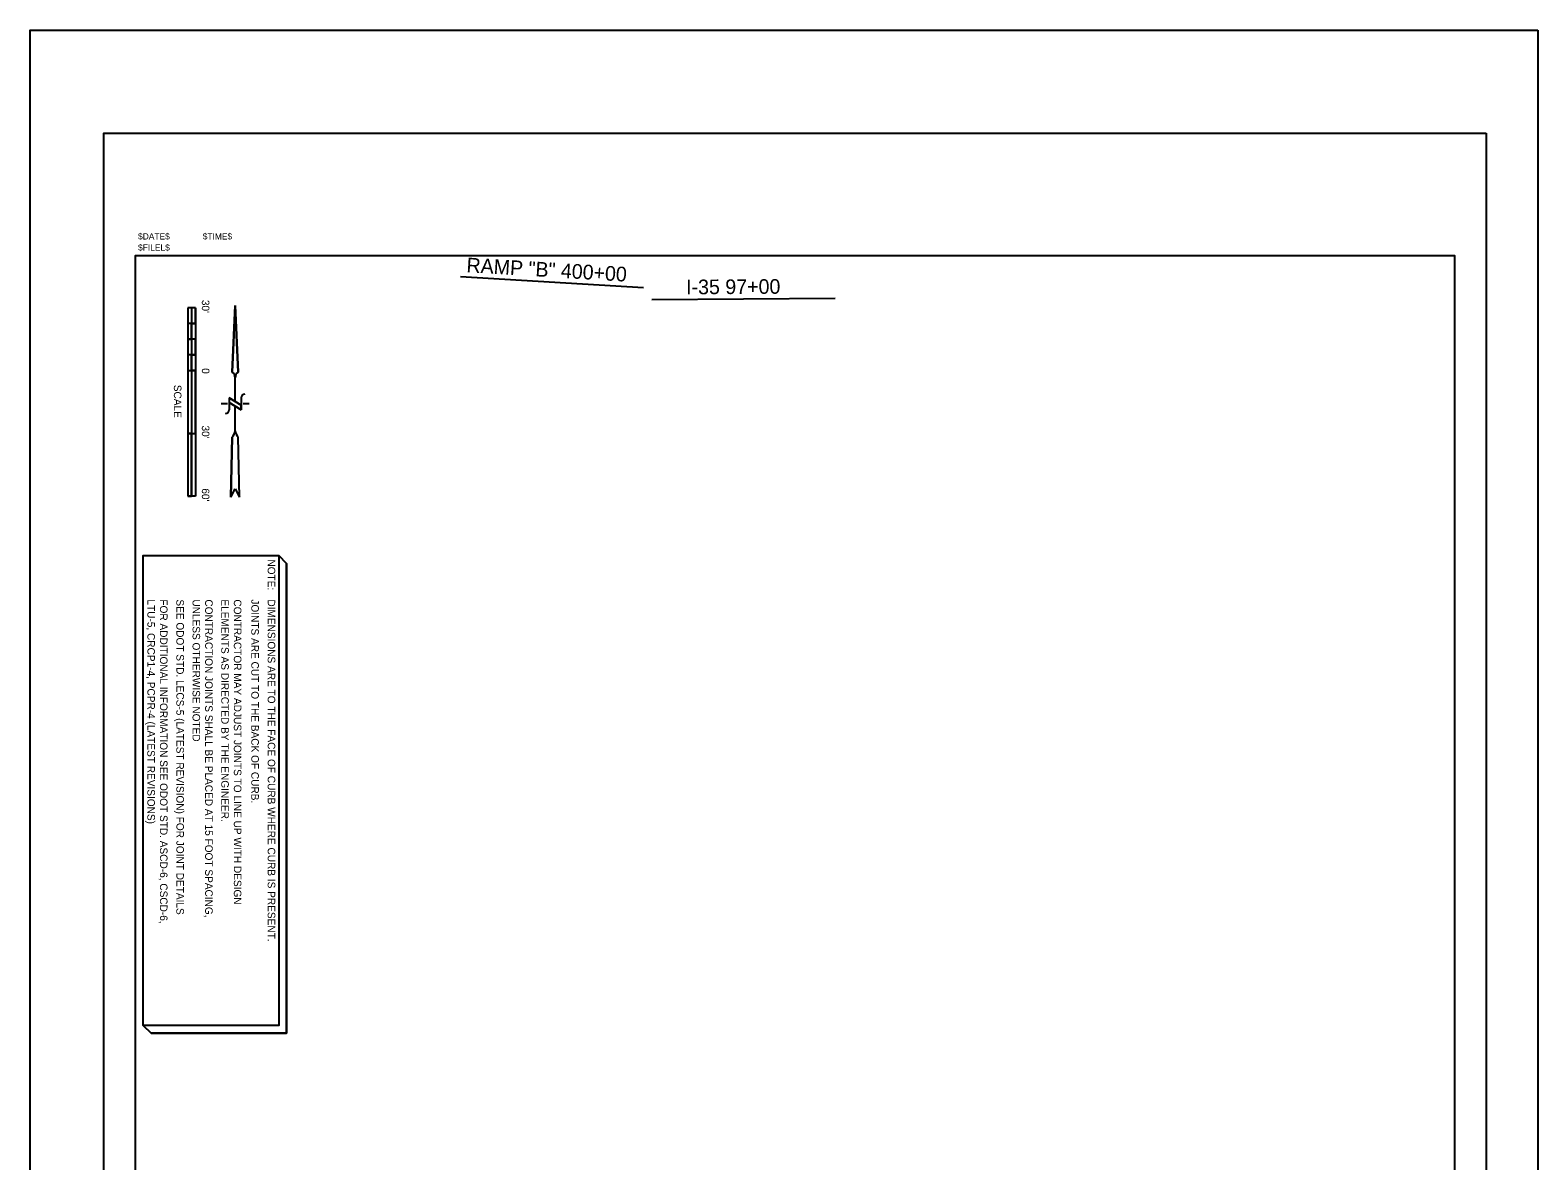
# Model space of a CAD drawing. Extents: x 2150474 to 2151194, y 143768 to 144848.
# Drawn here: x 2150474 to 2151194, y 144308 to 144848 of the extents above; entities that cross this region are included whole.
import ezdxf

# ---------------------------------------------------------------- set-up
doc = ezdxf.new("R2010")
doc.units = 0
for name, color, linetype in [('PR_Shading_1', 7, 'Continuous'), ('PR_Txt', 7, 'Continuous'), ('SHT_Match_Lines', 7, 'Continuous'), ('SHT_North_Arrow', 7, 'Continuous'), ('SHT_Plot_Shape_Full', 7, 'Continuous'), ('SHT_Plot_Shape_Half', 7, 'Continuous'), ('SHT_Plot_Stamp', 7, 'Continuous'), ('SHT_Scale', 7, 'Continuous'), ('SHT_Sheet_Border', 7, 'Continuous')]:
    doc.layers.add(name, color=color, linetype=linetype)

msp = doc.modelspace()

# ---------------------------------------------------------------- linework, layer by layer
at = {"layer": 'PR_Shading_1'}
msp.add_line((2150596.09, 144593.01), (2150592.34, 144596.76), dxfattribs=at)
for points in [[(2150592.34, 144596.76), (2150592.34, 144372.35), (2150527.66, 144372.35)], [(2150527.66, 144372.35), (2150531.41, 144368.6), (2150596.09, 144368.6), (2150596.09, 144593.01)]]:
    msp.add_lwpolyline(points, dxfattribs=at)
at = {"layer": 'PR_Txt'}
msp.add_lwpolyline([(2150592.34, 144596.76), (2150592.34, 144372.35), (2150527.66, 144372.35), (2150527.66, 144596.76)], close=True, dxfattribs=at)
msp.add_lwpolyline([(2150592.34, 144596.76), (2150596.09, 144593.01), (2150596.09, 144368.6), (2150531.41, 144368.6), (2150527.66, 144372.35)], dxfattribs=at)
at = {"layer": 'SHT_Match_Lines'}
for p, q in [((2150766.53, 144724.55), (2150679.09, 144729.79)), ((2150858.13, 144719.44), (2150770.53, 144718.92))]:
    msp.add_line(p, q, dxfattribs=at)
at = {"layer": 'SHT_North_Arrow'}
for p, q in [((2150570.1, 144684.38), (2150571.54, 144716.11)), ((2150571.54, 144716.11), (2150570.1, 144684.38)), ((2150571.54, 144716.11), (2150572.98, 144684.38)), ((2150572.98, 144684.38), (2150571.54, 144716.11)), ((2150571.54, 144670.35), (2150571.54, 144681.57)), ((2150574.42, 144668.62), (2150568.66, 144672.07)), ((2150568.66, 144672.07), (2150574.42, 144668.62)), ((2150568.66, 144672.07), (2150568.66, 144666.32)), ((2150571.54, 144670.35), (2150568.66, 144672.07)), ((2150568.66, 144672.07), (2150568.66, 144669.77)), ((2150574.42, 144666.32), (2150568.66, 144669.77)), ((2150574.42, 144668.62), (2150571.54, 144670.35)), ((2150574.42, 144672.07), (2150574.42, 144666.32)), ((2150567.8, 144669.19), (2150564.92, 144669.19)), ((2150571.54, 144656.24), (2150571.54, 144668.04)), ((2150574.42, 144666.32), (2150574.42, 144668.62)), ((2150578.16, 144669.19), (2150575.28, 144669.19)), ((2150569.53, 144624.58), (2150570.1, 144653.36)), ((2150570.1, 144653.36), (2150569.53, 144624.58)), ((2150573.56, 144624.58), (2150572.98, 144653.36)), ((2150573.56, 144624.58), (2150572.98, 144653.36)), ((2150569.53, 144624.58), (2150571.54, 144628.61)), ((2150569.53, 144624.58), (2150571.54, 144628.61)), ((2150571.54, 144628.61), (2150573.56, 144624.58)), ((2150571.54, 144628.61), (2150573.56, 144624.58))]:
    msp.add_line(p, q, dxfattribs=at)
for points in [[(2150568.66, 144669.77), (2150571.54, 144668.04), (2150574.42, 144666.32)], [(2150571.54, 144656.24), (2150571.54, 144656.24), (2150571.54, 144656.24)]]:
    msp.add_lwpolyline(points, dxfattribs=at)
for centre, radius, start, end in [((2150568.09, 144681.57), 3.45, 360, 54.38016), ((2150568.09, 144681.57), 3.45, 360, 54.38016), ((2150574.99, 144681.57), 3.45, 125.61984, 180), ((2150574.99, 144681.57), 3.45, 125.61984, 180), ((2150576.15, 144672.07), 1.73, 90, 180), ((2150566.93, 144666.32), 1.73, 270, 0), ((2150566.53, 144656.94), 5.06, 314.95671, 352.41889), ((2150566.53, 144656.94), 5.06, 314.95671, 352.059), ((2150576.55, 144656.94), 5.06, 187.58111, 225.04329), ((2150576.55, 144656.94), 5.06, 187.941, 225.04329)]:
    msp.add_arc(centre, radius, start, end, dxfattribs=at)
at = {"layer": 'SHT_Plot_Shape_Full'}
msp.add_lwpolyline([(2151193.63, 144847.67), (2151193.63, 143767.67), (2150473.63, 143767.67), (2150473.63, 144847.67)], close=True, dxfattribs=at)
at = {"layer": 'SHT_Plot_Shape_Half'}
msp.add_lwpolyline([(2151168.88, 144798.55), (2151168.88, 143778.55), (2150508.88, 143778.55), (2150508.88, 144798.55)], close=True, dxfattribs=at)
at = {"layer": 'SHT_Scale'}
for p, q in [((2150552.63, 144715.05), (2150548.88, 144715.05)), ((2150548.88, 144715.05), (2150548.88, 144625.05)), ((2150550.76, 144715.05), (2150550.76, 144707.55)), ((2150552.63, 144715.05), (2150550.76, 144715.05)), ((2150550.76, 144715.05), (2150550.76, 144707.55)), ((2150552.63, 144715.05), (2150552.63, 144625.05)), ((2150552.63, 144707.55), (2150552.63, 144715.05)), ((2150552.63, 144707.55), (2150548.88, 144707.55)), ((2150550.76, 144707.55), (2150548.88, 144707.55)), ((2150548.88, 144707.55), (2150548.88, 144700.05)), ((2150550.76, 144707.55), (2150550.76, 144700.05)), ((2150550.76, 144707.55), (2150552.63, 144707.55)), ((2150550.76, 144700.05), (2150550.76, 144707.55)), ((2150552.63, 144700.05), (2150548.88, 144700.05)), ((2150552.63, 144700.05), (2150548.88, 144700.05)), ((2150548.88, 144700.05), (2150550.76, 144700.05)), ((2150550.76, 144700.05), (2150550.76, 144692.55)), ((2150552.63, 144700.05), (2150550.76, 144700.05)), ((2150550.76, 144700.05), (2150550.76, 144692.55)), ((2150552.63, 144692.55), (2150552.63, 144700.05)), ((2150552.63, 144692.55), (2150548.88, 144692.55)), ((2150550.76, 144692.55), (2150548.88, 144692.55)), ((2150548.88, 144692.55), (2150548.88, 144685.05)), ((2150550.76, 144692.55), (2150550.76, 144685.05)), ((2150550.76, 144692.55), (2150552.63, 144692.55)), ((2150550.76, 144685.05), (2150550.76, 144692.55)), ((2150548.88, 144685.05), (2150550.76, 144685.05)), ((2150548.88, 144685.05), (2150550.76, 144685.05)), ((2150550.76, 144685.05), (2150552.63, 144685.05)), ((2150550.76, 144685.05), (2150550.76, 144625.05)), ((2150552.63, 144685.05), (2150550.76, 144685.05)), ((2150550.76, 144685.05), (2150550.76, 144655.05)), ((2150552.63, 144655.05), (2150552.63, 144685.05)), ((2150548.88, 144655.05), (2150550.76, 144655.05)), ((2150550.76, 144655.05), (2150548.88, 144655.05)), ((2150548.88, 144655.05), (2150548.88, 144625.05)), ((2150550.76, 144655.05), (2150552.63, 144655.05)), ((2150550.76, 144655.05), (2150552.63, 144655.05)), ((2150550.76, 144625.05), (2150550.76, 144655.05)), ((2150550.76, 144625.05), (2150548.88, 144625.05)), ((2150548.88, 144625.05), (2150550.76, 144625.05)), ((2150552.63, 144625.05), (2150550.76, 144625.05))]:
    msp.add_line(p, q, dxfattribs=at)
at = {"layer": 'SHT_Sheet_Border'}
msp.add_lwpolyline([(2150523.88, 143795.05), (2150523.88, 144740.05), (2151153.88, 144740.05), (2151153.88, 143795.05)], close=True, dxfattribs=at)

# ---------------------------------------------------------------- texts
at = {"layer": 'PR_Txt'}
for s, height, rotation, p in [('RAMP "B" 400+00', 7, 356.60129, (2150681.86, 144732.09)), ('I-35 97+00', 7, 0.38073, (2150786.9, 144721.49)), ('NOTE:', 3.6, 270, (2150587.08, 144594.91)), ('LTU-5, CRCP1-4, PCPR-4 (LATEST REVISIONS)', 3.6, 270, (2150529.62, 144575.81)), ('FOR ADDITIONAL INFORMATION SEE ODOT STD. ASCD-6, CSCD-6,', 3.6, 270, (2150535.63, 144575.81)), ('SEE ODOT STD. LECS-5 (LATEST REVISION) FOR JOINT DETAILS', 3.6, 270, (2150543.47, 144575.81)), ('UNLESS OTHERWISE NOTED', 3.6, 270, (2150551.19, 144575.81)), ('CONTRACTION JOINTS SHALL BE PLACED AT 15 FOOT SPACING,', 3.6, 270, (2150557.2, 144575.81)), ('ELEMENTS AS DIRECTED BY THE ENGINEER.', 3.6, 270, (2150564.9, 144575.81)), ('CONTRACTOR MAY ADJUST JOINTS TO LINE UP WITH DESIGN', 3.6, 270, (2150570.91, 144575.81)), ('JOINTS ARE CUT TO THE BACK OF CURB.', 3.6, 270, (2150579.25, 144575.81)), ('DIMENSIONS ARE TO THE FACE OF CURB WHERE CURB IS PRESENT.', 3.6, 270, (2150587.08, 144575.81))]:
    msp.add_text(s, height=height, rotation=rotation, dxfattribs=at).set_placement(p)
at = {"layer": 'SHT_Plot_Stamp'}
for s, p in [('$DATE$', (2150525.16, 144747.69)), ('$TIME$', (2150556.05, 144747.69)), ('$FILEL$', (2150525.16, 144742.37))]:
    msp.add_text(s, height=3, rotation=360, dxfattribs=at).set_placement(p)
at = {"layer": 'SHT_Scale'}
for s, p in [("30'", (2150555.63, 144718.86)), ('0', (2150555.63, 144686.23)), ('SCALE', (2150542.28, 144678.3)), ("30'", (2150555.63, 144658.86)), ("60'", (2150555.63, 144628.86))]:
    msp.add_text(s, height=3.6, rotation=270, dxfattribs=at).set_placement(p)

doc.saveas('drawing.dxf')
